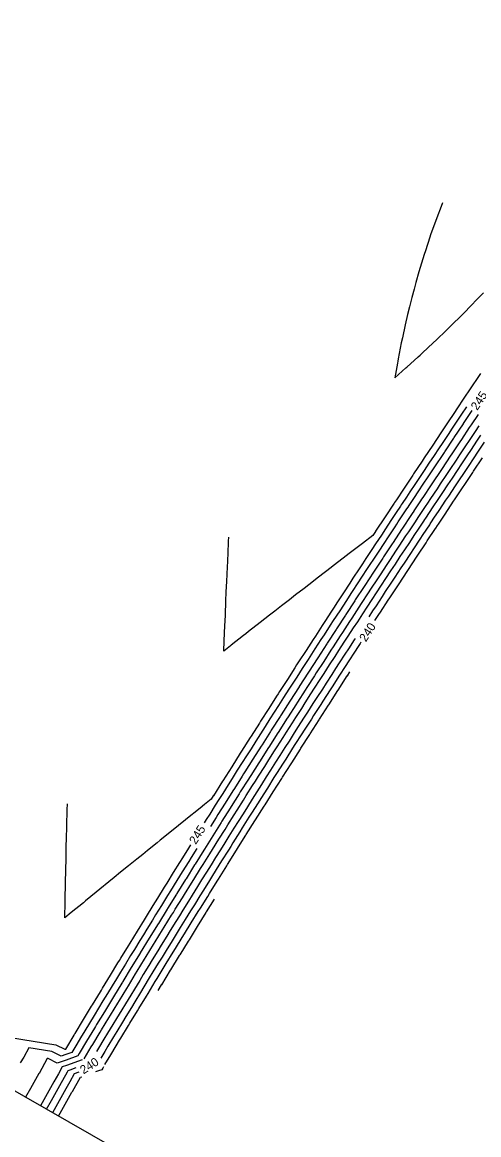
# Model space of a CAD drawing. Extents: x 1160447 to 1162032, y 616022 to 618272.
# Drawn here: x 1160642.1 to 1160773.9, y 616238.7 to 616560 of the extents above; entities that cross this region are included whole.
import ezdxf

# ---------------------------------------------------------------- set-up
doc = ezdxf.new("R2010")
doc.units = 0
for name, color, linetype in [('D_Contours_Major', 7, 'Continuous'), ('D_Contours_Minor', 7, 'Continuous'), ('Plot Boundary_1', 7, 'Continuous')]:
    doc.layers.add(name, color=color, linetype=linetype)

msp = doc.modelspace()

# ---------------------------------------------------------------- linework, layer by layer
at = {"layer": 'D_Contours_Major'}
for points in [[(1160694.71, 616328.78), (1160695.32, 616329.75), (1160696.32, 616331.33), (1160697.91, 616333.87), (1160698.96, 616335.55), (1160700.07, 616337.3), (1160701.61, 616339.76), (1160702.78, 616341.61), (1160704.27, 616343.97), (1160705.7, 616346.22), (1160706.93, 616348.17), (1160708.23, 616350.21), (1160709.6, 616352.37), (1160710.96, 616354.51), (1160712.27, 616356.57), (1160713.69, 616358.8), (1160714.95, 616360.76), (1160716.15, 616362.64), (1160717.63, 616364.95), (1160719.18, 616367.37), (1160720.31, 616369.14), (1160721.4, 616370.83), (1160723.01, 616373.33), (1160724.69, 616375.93), (1160725.7, 616377.51), (1160726.67, 616379.01), (1160728.4, 616381.69), (1160729.32, 616383.1), (1160731.11, 616385.86), (1160731.96, 616387.18), (1160733.82, 616390.03), (1160735.76, 616393.01), (1160736.53, 616394.2), (1160737.27, 616395.33), (1160739.26, 616398.36), (1160739.94, 616399.4), (1160741.98, 616402.52), (1160744.12, 616405.79), (1160744.71, 616406.68), (1160746.92, 616410.04), (1160747.45, 616410.84), (1160749.72, 616414.28), (1160750.19, 616414.99), (1160750.63, 616415.66), (1160752.93, 616419.13), (1160753.4, 616419.85), (1160753.48, 616419.96), (1160753.78, 616420.42), (1160755.68, 616423.28), (1160756.01, 616423.77), (1160758.43, 616427.42), (1160758.7, 616427.83), (1160761.18, 616431.57), (1160763.77, 616435.46), (1160763.93, 616435.71), (1160764.09, 616435.95), (1160766.69, 616439.85), (1160766.8, 616440.01), (1160769.44, 616443.99), (1160769.5, 616444.08), (1160771.99, 616447.82)], [(1160743.9, 616387.18), (1160745.03, 616388.92), (1160745.48, 616389.61), (1160747.74, 616393.08), (1160748.17, 616393.73), (1160750.46, 616397.23), (1160750.87, 616397.85), (1160753.19, 616401.38), (1160753.58, 616401.97), (1160755.92, 616405.52), (1160756.29, 616406.09), (1160758.65, 616409.66), (1160759.01, 616410.2), (1160761.39, 616413.8), (1160761.46, 616413.9), (1160761.94, 616414.63), (1160762.21, 616415.03), (1160764.13, 616417.93), (1160766.59, 616421.63), (1160766.87, 616422.07), (1160769.36, 616425.82), (1160769.62, 616426.2), (1160772.14, 616430), (1160772.37, 616430.33), (1160774.94, 616434.21)], [(1160739.82, 616380.92), (1160739.62, 616380.6), (1160737.42, 616377.22), (1160736.92, 616376.44), (1160734.75, 616373.09), (1160734.22, 616372.27), (1160733.68, 616371.43), (1160731.53, 616368.1), (1160730.96, 616367.22), (1160728.85, 616363.93), (1160728.25, 616362.99), (1160726.17, 616359.75), (1160725.54, 616358.77), (1160723.49, 616355.57), (1160722.84, 616354.54), (1160720.82, 616351.39), (1160720.14, 616350.31), (1160718.16, 616347.2), (1160717.44, 616346.07), (1160715.5, 616343.01), (1160714.75, 616341.84), (1160712.84, 616338.81), (1160710.97, 616335.85), (1160710.19, 616334.62), (1160708.28, 616331.59), (1160707.54, 616330.42), (1160705.59, 616327.31), (1160704.9, 616326.21), (1160702.91, 616323.03), (1160702.27, 616322), (1160701.61, 616320.95), (1160699.64, 616317.79), (1160698.85, 616316.54), (1160697.01, 616313.58), (1160696.12, 616312.14), (1160694.39, 616309.36), (1160693.39, 616307.76), (1160691.77, 616305.14), (1160690.69, 616303.38), (1160689.16, 616300.92), (1160687.71, 616298.56), (1160686.56, 616296.69), (1160685.07, 616294.28), (1160683.96, 616292.46), (1160682.44, 616290), (1160681.36, 616288.23), (1160679.83, 616285.73), (1160678.77, 616284), (1160677.21, 616281.44), (1160676.18, 616279.76), (1160674.6, 616277.15), (1160673.6, 616275.51), (1160671.99, 616272.86), (1160671.03, 616271.27), (1160669.4, 616268.58), (1160668.45, 616267.02), (1160666.81, 616264.29), (1160665.89, 616262.77), (1160664.74, 616260.85)], [(1160638.7, 616266.82), (1160651.75, 616264.72), (1160654.37, 616263.45), (1160654.46, 616263.4), (1160654.54, 616263.43), (1160654.64, 616263.47), (1160657.09, 616267.53), (1160657.21, 616267.74), (1160657.34, 616267.95), (1160659.78, 616272), (1160662.12, 616275.87), (1160662.36, 616276.26), (1160664.65, 616280.03), (1160664.94, 616280.51), (1160665.25, 616281.02), (1160667.53, 616284.77), (1160669.71, 616288.35), (1160670.12, 616289.02), (1160670.55, 616289.71), (1160672.72, 616293.26), (1160673.2, 616294.06), (1160675.32, 616297.51), (1160677.35, 616300.8), (1160677.93, 616301.75), (1160679.9, 616304.94), (1160680.54, 616305.98), (1160681.21, 616307.07), (1160683.16, 616310.22), (1160683.89, 616311.4), (1160685.78, 616314.45), (1160687.59, 616317.36), (1160688.4, 616318.67), (1160690.16, 616321.49), (1160690.75, 616322.44)], [(1160658.46, 616256.8), (1160657.12, 616256.33), (1160655.86, 616254.06), (1160654.7, 616251.99), (1160652.25, 616247.67), (1160650.8, 616245.11)]]:
    msp.add_lwpolyline(points, dxfattribs=at)
at = {"layer": 'D_Contours_Minor'}
for points in [[(1160763.35, 616507.77), (1160763.27, 616507.57), (1160763.26, 616507.56), (1160763.26, 616507.55), (1160761.45, 616502.75), (1160759.98, 616498.55), (1160759.74, 616497.87), (1160758.47, 616494), (1160758.12, 616492.93), (1160757.73, 616491.65), (1160756.6, 616487.94), (1160755.73, 616484.83), (1160755.18, 616482.89), (1160754.56, 616480.47), (1160753.86, 616477.77), (1160753.34, 616475.57), (1160752.64, 616472.6), (1160751.82, 616468.81), (1160751.51, 616467.37), (1160750.62, 616462.79), (1160750.48, 616462.08), (1160750.38, 616461.53), (1160749.65, 616457.31), (1160752.84, 616460.14), (1160753.12, 616460.39), (1160756.37, 616463.35), (1160756.94, 616463.87), (1160757.6, 616464.49), (1160760.71, 616467.39), (1160761.67, 616468.3), (1160764.42, 616470.94), (1160766.76, 616473.24), (1160768.07, 616474.52), (1160769.54, 616476), (1160771.66, 616478.14), (1160773.35, 616479.88), (1160775.2, 616481.79)], [(1160774.35, 616458.57), (1160773.76, 616457.68), (1160771.59, 616454.43), (1160769.36, 616451.08), (1160768.83, 616450.29), (1160768.32, 616449.52), (1160766.07, 616446.15), (1160765.61, 616445.45), (1160763.32, 616442), (1160762.9, 616441.38), (1160760.56, 616437.86), (1160758.13, 616434.2), (1160757.81, 616433.71), (1160757.5, 616433.24), (1160755.05, 616429.57), (1160754.8, 616429.18), (1160752.3, 616425.42), (1160752.14, 616425.18), (1160750.1, 616422.1), (1160749.58, 616421.31), (1160749.55, 616421.27), (1160749.41, 616421.06), (1160746.8, 616417.12), (1160744.08, 616412.99), (1160744.06, 616412.96), (1160743.28, 616411.78), (1160740.26, 616409.47), (1160736.09, 616406.26), (1160736.05, 616406.23), (1160735.99, 616406.19), (1160731.83, 616402.98), (1160731.22, 616402.51), (1160727.62, 616399.73), (1160724.78, 616397.53), (1160723.42, 616396.47), (1160721.01, 616394.61), (1160719.21, 616393.21), (1160716.94, 616391.44), (1160715.01, 616389.94), (1160713.48, 616388.74), (1160710.81, 616386.66), (1160707.44, 616384.02), (1160706.61, 616383.37), (1160705.96, 616382.86), (1160702.42, 616380.08), (1160702.2, 616379.9), (1160700.29, 616378.4), (1160700.4, 616381.31), (1160700.58, 616385.75), (1160700.64, 616387.03), (1160700.72, 616388.86), (1160700.88, 616392.76), (1160701, 616395.5), (1160701.13, 616398.49), (1160701.32, 616402.73), (1160701.39, 616404.22), (1160701.64, 616409.67), (1160701.66, 616409.95), (1160701.67, 616410.14), (1160701.72, 616411.27)], [(1160770.33, 616448.93), (1160768.91, 616446.8), (1160767.76, 616445.07), (1160766.2, 616442.73), (1160765, 616440.93), (1160763.5, 616438.66), (1160762.25, 616436.78), (1160760.95, 616434.83), (1160759.49, 616432.64), (1160758.1, 616430.54), (1160756.74, 616428.49), (1160755.4, 616426.48), (1160753.99, 616424.35), (1160752.96, 616422.8), (1160751.79, 616421.03), (1160751.49, 616420.58), (1160751.24, 616420.2), (1160750.02, 616418.36), (1160748.49, 616416.05), (1160746.9, 616413.64), (1160745.75, 616411.9), (1160744.1, 616409.39), (1160743.02, 616407.74), (1160741.3, 616405.13), (1160740.28, 616403.58), (1160739.31, 616402.1), (1160737.56, 616399.42), (1160736.65, 616398.03), (1160734.84, 616395.25), (1160732.94, 616392.35), (1160732.12, 616391.08), (1160731.33, 616389.87), (1160729.41, 616386.91), (1160728.68, 616385.79), (1160726.7, 616382.73), (1160726.03, 616381.71), (1160724, 616378.55), (1160721.87, 616375.26), (1160721.3, 616374.37), (1160720.76, 616373.52), (1160718.61, 616370.19), (1160716.37, 616366.69), (1160715.92, 616366), (1160715.5, 616365.33), (1160713.24, 616361.8), (1160710.88, 616358.11), (1160710.56, 616357.61), (1160708.15, 616353.81), (1160707.89, 616353.41), (1160705.42, 616349.51), (1160705.22, 616349.2), (1160705.03, 616348.91), (1160702.56, 616345), (1160699.97, 616340.91), (1160699.9, 616340.79), (1160697.26, 616336.6), (1160697.23, 616336.55), (1160696.66, 616335.64), (1160694.67, 616334.05), (1160693.43, 616333.06), (1160689.35, 616329.79), (1160689.28, 616329.73), (1160689.19, 616329.66), (1160685.14, 616326.39), (1160681.94, 616323.81), (1160681, 616323.05), (1160678.23, 616320.81), (1160676.86, 616319.7), (1160675.14, 616318.31), (1160672.73, 616316.35), (1160670.47, 616314.51), (1160668.6, 616312.99), (1160667.12, 616311.78), (1160664.47, 616309.62), (1160663.42, 616308.76), (1160660.35, 616306.24), (1160659.73, 616305.74), (1160656.22, 616302.86), (1160654.39, 616301.36), (1160654.43, 616303.52), (1160654.44, 616303.9), (1160654.52, 616308.4), (1160654.55, 616309.63), (1160654.59, 616311.38), (1160654.67, 616315.36), (1160654.74, 616318.32), (1160654.8, 616321.09), (1160654.9, 616325.26), (1160654.93, 616326.82), (1160654.96, 616327.92), (1160655.08, 616332.56), (1160655.12, 616334.25)], [(1160773.66, 616446.71), (1160771.64, 616443.68), (1160771.13, 616442.91), (1160768.86, 616439.5), (1160768.37, 616438.77), (1160766.07, 616435.31), (1160765.62, 616434.63), (1160763.29, 616431.13), (1160762.87, 616430.49), (1160760.51, 616426.95), (1160760.12, 616426.35), (1160757.74, 616422.76), (1160757.37, 616422.21), (1160757.08, 616421.78), (1160755.17, 616418.9), (1160755.1, 616418.79), (1160754.62, 616418.07), (1160754.29, 616417.57), (1160751.88, 616413.92), (1160751.58, 616413.46), (1160749.14, 616409.77), (1160748.87, 616409.36), (1160746.41, 616405.62), (1160746.16, 616405.24), (1160743.68, 616401.46), (1160743.46, 616401.13), (1160740.95, 616397.31), (1160740.76, 616397.01), (1160738.23, 616393.14), (1160738.07, 616392.9), (1160735.52, 616388.98), (1160735.39, 616388.77), (1160732.81, 616384.81), (1160732.71, 616384.65), (1160730.11, 616380.64), (1160730.03, 616380.52), (1160727.41, 616376.46), (1160724.73, 616372.31), (1160724.71, 616372.28), (1160722.05, 616368.14), (1160722.02, 616368.1), (1160721.99, 616368.06), (1160719.34, 616363.91), (1160716.8, 616359.95), (1160716.66, 616359.72), (1160716.51, 616359.49), (1160713.98, 616355.53), (1160713.77, 616355.2), (1160711.31, 616351.34), (1160711.04, 616350.91), (1160708.64, 616347.14), (1160706.36, 616343.53), (1160705.98, 616342.94), (1160705.59, 616342.31), (1160703.33, 616338.73), (1160702.88, 616338.01), (1160700.68, 616334.52), (1160698.58, 616331.18), (1160698.03, 616330.31), (1160696.41, 616327.72)], [(1160773.87, 616443.42), (1160772.81, 616441.83), (1160771.08, 616439.23), (1160770.06, 616437.69), (1160768.29, 616435.04), (1160767.31, 616433.56), (1160765.5, 616430.84), (1160764.56, 616429.42), (1160762.73, 616426.66), (1160761.81, 616425.28), (1160759.95, 616422.48), (1160759.06, 616421.14), (1160758.36, 616420.09), (1160756.86, 616417.83), (1160756.69, 616417.57), (1160756.31, 616417), (1160755.47, 616415.73), (1160753.57, 616412.86), (1160752.75, 616411.62), (1160750.83, 616408.71), (1160750.04, 616407.51), (1160748.1, 616404.56), (1160747.34, 616403.4), (1160745.37, 616400.41), (1160744.64, 616399.28), (1160742.65, 616396.25), (1160741.94, 616395.16), (1160739.93, 616392.09), (1160739.25, 616391.04), (1160737.22, 616387.92), (1160736.57, 616386.92), (1160734.51, 616383.76), (1160733.88, 616382.79), (1160731.81, 616379.59), (1160731.21, 616378.66), (1160729.11, 616375.41), (1160726.97, 616372.09), (1160726.42, 616371.24), (1160724.25, 616367.86), (1160723.73, 616367.06), (1160721.53, 616363.63), (1160721.04, 616362.87), (1160718.82, 616359.4), (1160718.36, 616358.69), (1160716.12, 616355.17), (1160715.69, 616354.5), (1160713.42, 616350.93), (1160713.02, 616350.3), (1160710.72, 616346.68), (1160710.36, 616346.11), (1160708.04, 616342.44), (1160707.7, 616341.91), (1160707.37, 616341.38), (1160705.04, 616337.7), (1160704.73, 616337.21), (1160702.39, 616333.5), (1160702.1, 616333.03), (1160699.75, 616329.29), (1160699.48, 616328.85), (1160697.11, 616325.07), (1160694.69, 616321.2), (1160694.48, 616320.86), (1160692.02, 616316.91), (1160691.85, 616316.64), (1160689.36, 616312.63), (1160689.22, 616312.41), (1160686.7, 616308.35), (1160686.6, 616308.19), (1160684.06, 616304.07), (1160683.99, 616303.96), (1160683.92, 616303.85), (1160681.38, 616299.72), (1160681.34, 616299.66), (1160678.77, 616295.49), (1160678.76, 616295.47), (1160676.17, 616291.25), (1160676.15, 616291.2), (1160673.58, 616287.01), (1160671.13, 616282.99), (1160670.99, 616282.76), (1160670.84, 616282.52), (1160668.41, 616278.51), (1160666.08, 616274.68), (1160665.83, 616274.26), (1160663.56, 616270.52), (1160663.25, 616270.01), (1160662.93, 616269.47), (1160660.68, 616265.75), (1160658.54, 616262.19), (1160658.12, 616261.49), (1160654.77, 616260.31), (1160652.17, 616259.39), (1160649.53, 616260.74), (1160649.49, 616260.75), (1160649.3, 616260.79), (1160646.94, 616256.42), (1160646.91, 616256.38), (1160644.47, 616252.07), (1160643.05, 616249.55)], [(1160659.98, 616260.7), (1160662.01, 616264.09), (1160662.42, 616264.75), (1160664.56, 616268.31), (1160664.99, 616269.01), (1160667.11, 616272.53), (1160667.56, 616273.26), (1160669.67, 616276.75), (1160670.14, 616277.51), (1160672.24, 616280.98), (1160672.72, 616281.76), (1160674.82, 616285.2), (1160675.31, 616286), (1160677.4, 616289.42), (1160677.9, 616290.24), (1160679.99, 616293.64), (1160680.5, 616294.48), (1160682.58, 616297.87), (1160683.1, 616298.71), (1160685.18, 616302.09), (1160685.71, 616302.95), (1160686.27, 616303.84), (1160688.33, 616307.17), (1160688.93, 616308.15), (1160690.95, 616311.4), (1160691.61, 616312.47), (1160693.57, 616315.62), (1160694.3, 616316.79), (1160696.2, 616319.84), (1160697, 616321.11), (1160698.83, 616324.05), (1160700.62, 616326.91), (1160701.47, 616328.26), (1160703.27, 616331.12), (1160704.11, 616332.47), (1160705.92, 616335.33), (1160706.76, 616336.67), (1160708.57, 616339.54), (1160709.41, 616340.87), (1160710.28, 616342.24), (1160712.07, 616345.07), (1160712.96, 616346.48), (1160714.73, 616349.27), (1160715.66, 616350.72), (1160717.4, 616353.46), (1160718.36, 616354.96), (1160720.07, 616357.65), (1160721.06, 616359.19), (1160722.75, 616361.83), (1160723.77, 616363.42), (1160725.43, 616366.01), (1160726.48, 616367.65), (1160728.12, 616370.19), (1160729.2, 616371.87), (1160730.81, 616374.37), (1160732.39, 616376.81), (1160733.51, 616378.54), (1160735.06, 616380.93), (1160736.21, 616382.71), (1160737.74, 616385.06), (1160738.92, 616386.87), (1160740.43, 616389.19), (1160741.63, 616391.03), (1160743.12, 616393.31), (1160744.35, 616395.19), (1160745.82, 616397.43), (1160747.07, 616399.35), (1160748.52, 616401.55), (1160749.8, 616403.5), (1160751.22, 616405.66), (1160752.53, 616407.65), (1160753.93, 616409.77), (1160755.26, 616411.79), (1160756.65, 616413.88), (1160758.01, 616415.93), (1160758.28, 616416.35), (1160758.55, 616416.76), (1160759.64, 616418.4), (1160760.75, 616420.07), (1160762.16, 616422.2), (1160763.5, 616424.21), (1160764.94, 616426.38), (1160766.24, 616428.35), (1160767.72, 616430.56), (1160768.99, 616432.48), (1160770.51, 616434.76), (1160771.74, 616436.62), (1160773.3, 616438.96), (1160774.49, 616440.75)], [(1160742.22, 616388.27), (1160743.33, 616389.98), (1160744.3, 616391.46), (1160746.05, 616394.13), (1160746.99, 616395.58), (1160748.77, 616398.29), (1160749.7, 616399.7), (1160751.49, 616402.44), (1160752.4, 616403.82), (1160754.22, 616406.58), (1160755.11, 616407.93), (1160756.96, 616410.73), (1160757.83, 616412.04), (1160759.7, 616414.87), (1160759.87, 616415.12), (1160760.25, 616415.69), (1160760.92, 616416.72), (1160762.44, 616419), (1160764.37, 616421.92), (1160765.19, 616423.14), (1160767.15, 616426.1), (1160767.93, 616427.27), (1160769.93, 616430.28), (1160770.68, 616431.41), (1160772.73, 616434.49), (1160773.43, 616435.54), (1160775.53, 616438.69)], [(1160738.15, 616382.01), (1160737.91, 616381.66), (1160736.24, 616379.08), (1160735.21, 616377.49), (1160733.57, 616374.95), (1160732.52, 616373.32), (1160731.44, 616371.65), (1160729.83, 616369.15), (1160728.72, 616367.43), (1160727.14, 616364.97), (1160726.01, 616363.21), (1160724.46, 616360.79), (1160723.3, 616358.98), (1160721.78, 616356.61), (1160720.6, 616354.75), (1160719.11, 616352.42), (1160717.9, 616350.51), (1160716.44, 616348.23), (1160715.2, 616346.28), (1160713.78, 616344.04), (1160712.51, 616342.04), (1160711.13, 616339.84), (1160709.77, 616337.7), (1160708.47, 616335.64), (1160707.1, 616333.46), (1160705.83, 616331.44), (1160704.43, 616329.22), (1160703.19, 616327.24), (1160701.77, 616324.97), (1160700.55, 616323.03), (1160699.3, 616321.03), (1160697.92, 616318.81), (1160696.58, 616316.66), (1160695.29, 616314.6), (1160693.86, 616312.3), (1160692.67, 616310.38), (1160691.16, 616307.95), (1160690.05, 616306.16), (1160688.48, 616303.61), (1160687.44, 616301.93), (1160686.45, 616300.32), (1160684.83, 616297.7), (1160683.83, 616296.07), (1160682.23, 616293.47), (1160681.22, 616291.82), (1160679.63, 616289.24), (1160678.61, 616287.57), (1160677.04, 616285), (1160676.02, 616283.32), (1160674.45, 616280.76), (1160673.42, 616279.06), (1160671.87, 616276.51), (1160670.83, 616274.8), (1160669.29, 616272.27), (1160668.26, 616270.55), (1160666.72, 616268.02), (1160665.69, 616266.3), (1160664.15, 616263.76), (1160663.53, 616262.73)], [(1160665.94, 616258.98), (1160667.62, 616261.77), (1160667.93, 616262.29), (1160670.19, 616266.02), (1160670.54, 616266.6), (1160672.76, 616270.27), (1160673.15, 616270.91), (1160675.33, 616274.51), (1160675.77, 616275.23), (1160677.91, 616278.75), (1160678.41, 616279.56), (1160680.5, 616282.99), (1160681.04, 616283.88), (1160683.09, 616287.23), (1160683.67, 616288.18), (1160685.68, 616291.46), (1160686.32, 616292.49), (1160688.28, 616295.68), (1160688.97, 616296.79), (1160690.89, 616299.91), (1160692.9, 616303.16), (1160693.5, 616304.13), (1160695.62, 616307.56), (1160696.11, 616308.35), (1160698.37, 616311.98), (1160698.73, 616312.56), (1160701.13, 616316.41), (1160701.36, 616316.77), (1160703.92, 616320.87), (1160703.99, 616320.98), (1160704.06, 616321.09), (1160706.62, 616325.19), (1160706.76, 616325.41), (1160709.26, 616329.39), (1160709.46, 616329.71), (1160711.91, 616333.59), (1160712.17, 616334.01), (1160714.55, 616337.78), (1160716.99, 616341.63), (1160717.21, 616341.97), (1160719.68, 616345.87), (1160719.87, 616346.16), (1160722.38, 616350.1), (1160722.53, 616350.35), (1160725.07, 616354.33), (1160725.2, 616354.53), (1160727.78, 616358.56), (1160727.87, 616358.71), (1160730.49, 616362.78), (1160730.55, 616362.88), (1160733.2, 616367), (1160733.24, 616367.06), (1160735.92, 616371.21), (1160735.93, 616371.24), (1160736.67, 616372.38)], [(1160692.45, 616321.38), (1160690.84, 616318.81), (1160690.13, 616317.65), (1160688.28, 616314.68), (1160687.5, 616313.43), (1160686.69, 616312.12), (1160684.88, 616309.2), (1160684.01, 616307.8), (1160682.26, 616304.97), (1160680.6, 616302.26), (1160679.65, 616300.73), (1160678.05, 616298.12), (1160677.05, 616296.5), (1160676, 616294.8), (1160674.45, 616292.26), (1160673.35, 616290.46), (1160671.85, 616288.01), (1160670.42, 616285.67), (1160669.26, 616283.76), (1160668.04, 616281.77), (1160666.67, 616279.51), (1160665.36, 616277.36), (1160664.09, 616275.26), (1160662.84, 616273.19), (1160661.52, 616271), (1160660.13, 616268.71), (1160658.95, 616266.74), (1160657.81, 616264.86), (1160656.38, 616262.48), (1160654.66, 616261.87), (1160653.31, 616261.4), (1160651.95, 616262.09), (1160650.62, 616262.73), (1160644, 616263.8), (1160642.55, 616261.12), (1160641.5, 616259.48)], [(1160697.46, 616306.73), (1160695.22, 616303.12), (1160695.11, 616302.93), (1160692.61, 616298.9), (1160690.23, 616295.03), (1160690.01, 616294.67), (1160687.56, 616290.69), (1160687.41, 616290.45), (1160684.9, 616286.36), (1160684.82, 616286.22), (1160682.25, 616282.03), (1160682.23, 616281.99), (1160681.24, 616280.37)], [(1160659.42, 616260.34), (1160654.89, 616258.75), (1160653.65, 616258.31), (1160652.55, 616256.34), (1160651.22, 616253.97), (1160648.76, 616249.64), (1160647.33, 616247.1)], [(1160649.06, 616246.1), (1160650.5, 616248.65), (1160652.96, 616252.98), (1160655.15, 616256.89), (1160655.38, 616257.32), (1160655.93, 616257.51), (1160657.62, 616258.11)], [(1160665.58, 616258.37), (1160665.33, 616257.97), (1160665.06, 616257.52), (1160664.07, 616257.17), (1160663.25, 616256.88)], [(1160652.53, 616244.11), (1160653.99, 616246.68), (1160656.44, 616251.01), (1160656.57, 616251.24), (1160658.86, 616255.34), (1160659.3, 616255.5)]]:
    msp.add_lwpolyline(points, dxfattribs=at)
at = {"layer": 'Plot Boundary_1'}
msp.add_lwpolyline([(1160500.57, 616331.28), (1160855.78, 616950.54), (1161275.71, 616709.67), (1160920.5, 616090.41)], close=True, dxfattribs=at)

# ---------------------------------------------------------------- texts
at = {"layer": 'D_Contours_Major'}
for s, rotation, p in [('245', 56.3165, (1160773.42, 616447.72)), ('240', 56.9507, (1160741.27, 616380.86)), ('245', 57.9908, (1160692.19, 616322.38)), ('240', 32.6534, (1160659.77, 616256.13))]:
    msp.add_text(s, height=2.49, rotation=rotation, dxfattribs=at).set_placement(p)

doc.saveas('drawing.dxf')
